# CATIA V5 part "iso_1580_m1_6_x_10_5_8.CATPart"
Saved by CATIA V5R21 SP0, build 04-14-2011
Part number: iso_1580_m1_6_x_10_5_8
Definition: Pan head screw ISO 1580 - M1.6 x 10 - 5.8
Description: Pan head screw ISO 1580 - M1.6 x 10 - 5.8
Property "REFERENCE": "ISO 1580 - M1.6 x 10 - 5.8"
Property "REFERENCE": "ISO 1580 - M1.6 x 10 - 5.8"
Property "PITCH": "0.35 mm"
Property "PITCH": "0.35 mm"
Property "MATERIAL": "Steel"
Property "MATERIAL": "Steel"
Property "DESIGN": "Pan head screw ISO 1580 - M1.6 x 10 - 5.8"
Property "DESIGN": "Pan head screw ISO 1580 - M1.6 x 10 - 5.8"
Property "NOMINAL_DIAMETER": "1.6 mm"
Property "NOMINAL_DIAMETER": "1.6 mm"
Property "STANDARD": "ISO 1580"
Property "STANDARD": "ISO 1580"
Property "LENGTH": "10 mm"
Property "LENGTH": "10 mm"
Property "TraceParts.PartVersion": "1.1.3"
Property "TraceParts.PartNumber": "33-08082018-064441"
Property "TraceParts.PartLanguage": "en"
Property "TraceParts.InstanceId": "33-08082018-06444172YU8PX2I59UZG3AWK3BZSD0Z"
Property "TraceParts.PartTitle": "Slotted pan head screws – Product grade A"
Property "TRACEPARTS": "TRACEPARTS"
Property "TraceParts.PartStandardAcronym": "ISO"
Publications: "Face", "Axis"
Bounding box of the stored display mesh (mm): x -1 to 10, y -1.6 to 1.6, z -1.599 to 1.599
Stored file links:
  C:\Users\zerma\Pictures\Stage Stomate\iso_1580_m1_6_x_10_5_8.CATPart
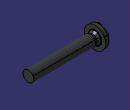
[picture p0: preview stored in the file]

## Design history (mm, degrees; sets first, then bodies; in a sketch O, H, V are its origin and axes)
AxisSystem1: origin (0, 0, 0), X (1, 0, 0), Y (0, 1, 0), Z (0, 0, 1)
Body1 "iso_1580_m1_6_x_10_5_8" (main body)
  Solid1: solid without history
  Thread1: diameter 1.6, depth 9.3, pitch 0.35, on face of Solid1, from face of Solid1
